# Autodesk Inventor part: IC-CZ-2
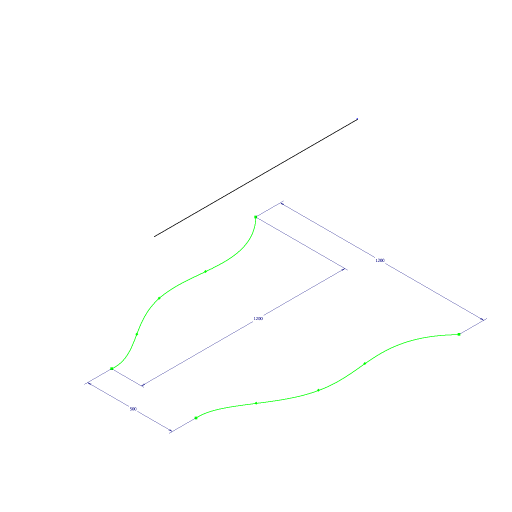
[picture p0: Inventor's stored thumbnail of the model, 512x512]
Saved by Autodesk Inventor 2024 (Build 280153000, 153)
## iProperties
Company: ATC
Created: 2023-03
Part Number: IC-CZ-2
Document SubType Name: Modeling
Designer: Andrzej Jaskulski
Density: 1 g/cm^3
Material: Kurs-AJ
Appearance: Kurs-AJ
Checked By: A.J.
Engr Approved By: Andrzej Jaskulski
Mfg Approved By: Andrzej Jaskulski
Authority: A.J.
Author: Andrzej Jaskulski
Revision Number: 1/24
Title: A.J.: Kurs R2024-MEP
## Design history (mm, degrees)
sketch "Szkic1"
  geometry: 10 further points
  constraints: 10 other
  dimensions: "d5" = 1200 distance of point (827.042, 1176.785) point (-372.958, 1176.785); "d6" = 500 horizontal distance of point (477.042, -25.6) point (-22.958, -23.215); "d7" = 1200 vertical distance of point (-372.958, 1176.785) point (-22.958, -23.215)
node "Płaszczyzna konstrukcyjna1"
sketch "Szkic2"
  geometry: L1 (227.042, -23.215)-(227.042, 1176.785); 1 further point
  constraints: 3 end point, 1 coincident, 1 vertical
